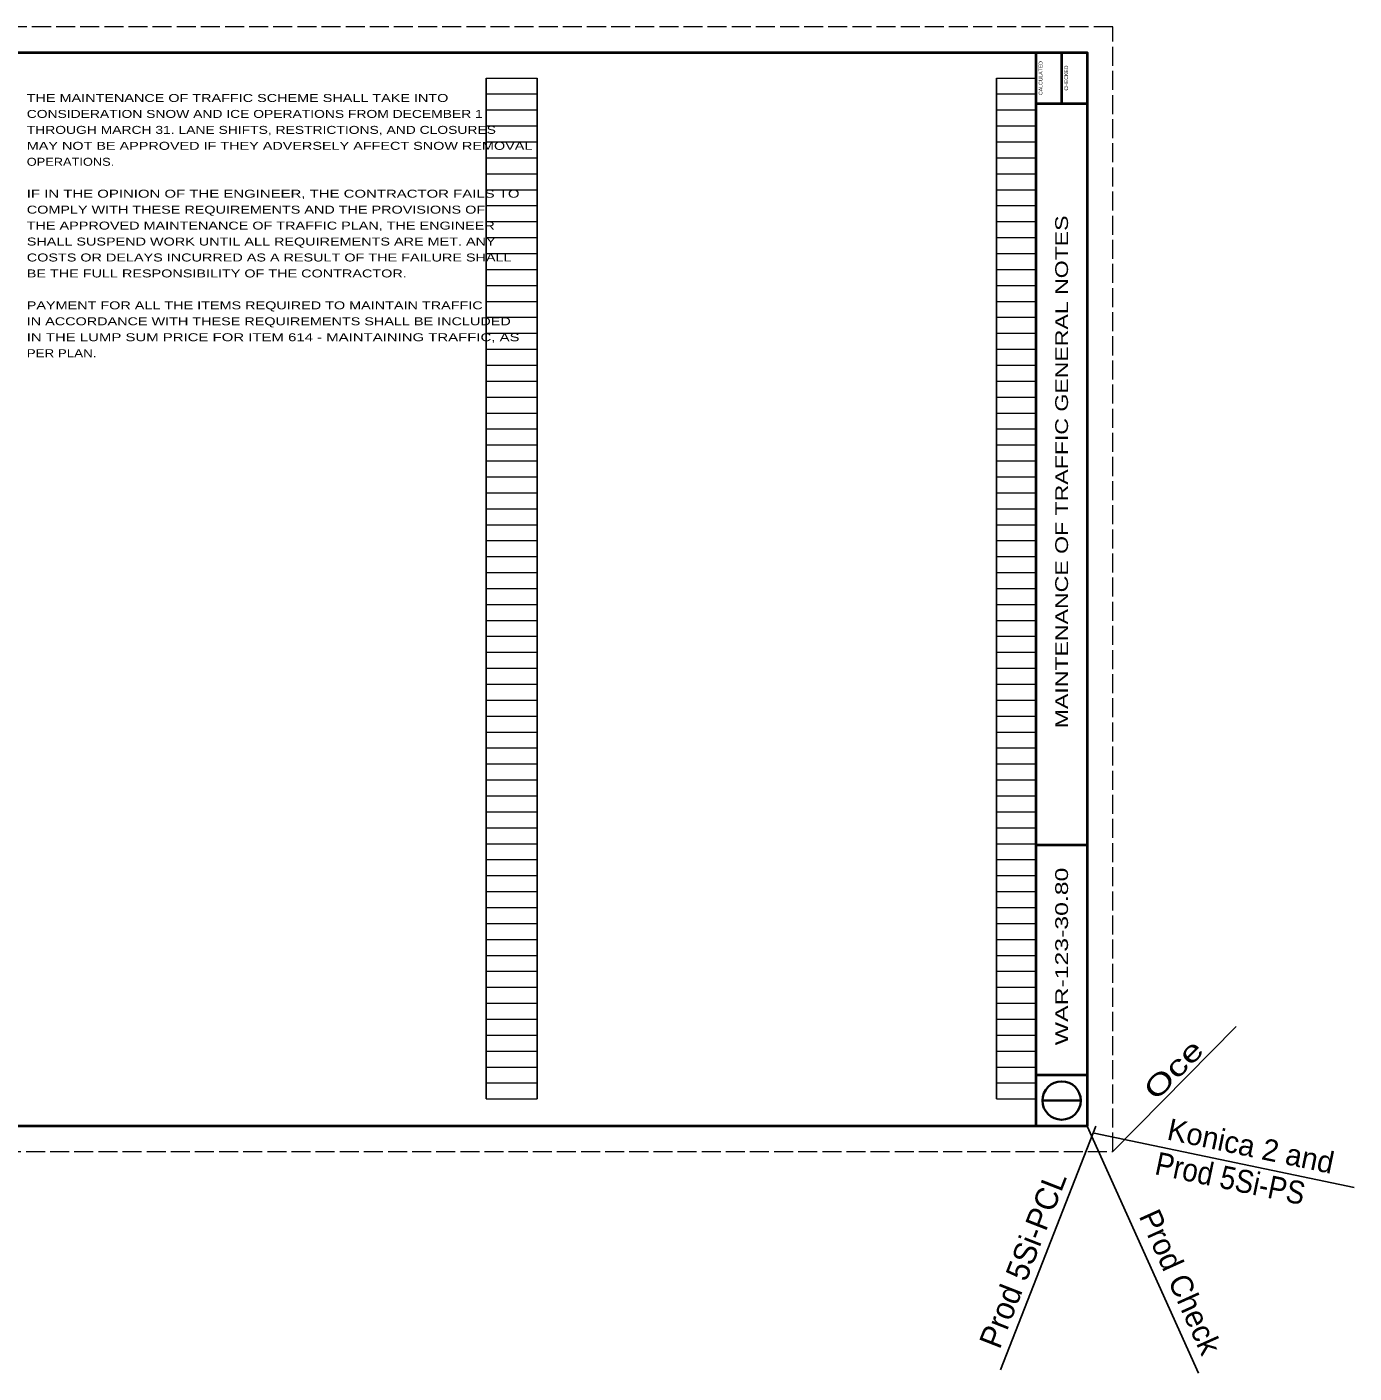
# Model space of a CAD drawing. Extents: x 28.3 to 71.4, y 8.1 to 38.
# Drawn here: x 45.44 to 71.39, y 8.14 to 34.47 of the extents above; entities that cross this region are included whole.
import ezdxf
from ezdxf.enums import TextEntityAlignment as Align

# ---------------------------------------------------------------- set-up
doc = ezdxf.new("R2010")
doc.units = 0
doc.header["$LTSCALE"] = 0.062
doc.linetypes.add('LONG_DASHED', pattern=[7.5, 6, -1.5])
doc.layers.add('1', color=7, linetype='Continuous', lineweight=13)
doc.layers.add('43', color=7, linetype='Continuous', lineweight=25)
doc.layers.add('44', color=7, linetype='Continuous')

msp = doc.modelspace()

# ---------------------------------------------------------------- linework, layer by layer
at = {"layer": '1', "lineweight": 40}
for p, q in [((65.17442, 12.96608), (65.17442, 33.96608)), ((65.67442, 33.96608), (65.67442, 32.96608)), ((65.17442, 32.96608), (66.17442, 32.96608)), ((65.17442, 18.46608), (66.17442, 18.46608)), ((65.17442, 13.96608), (66.17442, 13.96608))]:
    msp.add_line(p, q, dxfattribs=at)
at = {"layer": '1'}
for p, q in [((54.41642, 33.46608), (55.41642, 33.46608)), ((64.40042, 33.46608), (65.17442, 33.46608)), ((54.41642, 33.15408), (55.41642, 33.15408)), ((64.40042, 33.15408), (65.17442, 33.15408)), ((54.41642, 32.84208), (55.41642, 32.84208)), ((64.40042, 32.84208), (65.17442, 32.84208)), ((54.41642, 32.53008), (55.41642, 32.53008)), ((64.40042, 32.53008), (65.17442, 32.53008)), ((54.41642, 32.21808), (55.41642, 32.21808)), ((64.40042, 32.21808), (65.17442, 32.21808)), ((54.41642, 31.90608), (55.41642, 31.90608)), ((64.40042, 31.90608), (65.17442, 31.90608)), ((54.41642, 31.59408), (55.41642, 31.59408)), ((64.40042, 31.59408), (65.17442, 31.59408)), ((54.41642, 31.28208), (55.41642, 31.28208)), ((64.40042, 31.28208), (65.17442, 31.28208)), ((54.41642, 30.97008), (55.41642, 30.97008)), ((64.40042, 30.97008), (65.17442, 30.97008)), ((54.41642, 30.65808), (55.41642, 30.65808)), ((64.40042, 30.65808), (65.17442, 30.65808)), ((54.41642, 30.34608), (55.41642, 30.34608)), ((64.40042, 30.34608), (65.17442, 30.34608)), ((54.41642, 30.03408), (55.41642, 30.03408)), ((64.40042, 30.03408), (65.17442, 30.03408)), ((54.41642, 29.72208), (55.41642, 29.72208)), ((64.40042, 29.72208), (65.17442, 29.72208)), ((54.41642, 29.41008), (55.41642, 29.41008)), ((64.40042, 29.41008), (65.17442, 29.41008)), ((54.41642, 29.09808), (55.41642, 29.09808)), ((64.40042, 29.09808), (65.17442, 29.09808)), ((54.41642, 28.78608), (55.41642, 28.78608)), ((64.40042, 28.78608), (65.17442, 28.78608)), ((54.41642, 28.47408), (55.41642, 28.47408)), ((64.40042, 28.47408), (65.17442, 28.47408)), ((54.41642, 28.16208), (55.41642, 28.16208)), ((64.40042, 28.16208), (65.17442, 28.16208)), ((54.41642, 27.85008), (55.41642, 27.85008)), ((64.40042, 27.85008), (65.17442, 27.85008)), ((54.41642, 27.53808), (55.41642, 27.53808)), ((64.40042, 27.53808), (65.17442, 27.53808)), ((54.41642, 27.22608), (55.41642, 27.22608)), ((64.40042, 27.22608), (65.17442, 27.22608)), ((54.41642, 26.91408), (55.41642, 26.91408)), ((64.40042, 26.91408), (65.17442, 26.91408)), ((54.41642, 26.60208), (55.41642, 26.60208)), ((64.40042, 26.60208), (65.17442, 26.60208)), ((54.41642, 26.29008), (55.41642, 26.29008)), ((64.40042, 26.29008), (65.17442, 26.29008)), ((54.41642, 25.97808), (55.41642, 25.97808)), ((64.40042, 25.97808), (65.17442, 25.97808)), ((54.41642, 25.66608), (55.41642, 25.66608)), ((64.40042, 25.66608), (65.17442, 25.66608)), ((54.41642, 25.35408), (55.41642, 25.35408)), ((64.40042, 25.35408), (65.17442, 25.35408)), ((54.41642, 25.04208), (55.41642, 25.04208)), ((64.40042, 25.04208), (65.17442, 25.04208)), ((54.41642, 24.73008), (55.41642, 24.73008)), ((64.40042, 24.73008), (65.17442, 24.73008)), ((54.41642, 24.41808), (55.41642, 24.41808)), ((64.40042, 24.41808), (65.17442, 24.41808)), ((54.41642, 24.10608), (55.41642, 24.10608)), ((64.40042, 24.10608), (65.17442, 24.10608)), ((54.41642, 23.79408), (55.41642, 23.79408)), ((64.40042, 23.79408), (65.17442, 23.79408)), ((54.41642, 23.48208), (55.41642, 23.48208)), ((64.40042, 23.48208), (65.17442, 23.48208)), ((54.41642, 23.17008), (55.41642, 23.17008)), ((64.40042, 23.17008), (65.17442, 23.17008)), ((54.41642, 22.85808), (55.41642, 22.85808)), ((64.40042, 22.85808), (65.17442, 22.85808)), ((54.41642, 22.54608), (55.41642, 22.54608)), ((64.40042, 22.54608), (65.17442, 22.54608)), ((54.41642, 22.23408), (55.41642, 22.23408)), ((64.40042, 22.23408), (65.17442, 22.23408)), ((54.41642, 21.92208), (55.41642, 21.92208)), ((64.40042, 21.92208), (65.17442, 21.92208)), ((54.41642, 21.61008), (55.41642, 21.61008)), ((64.40042, 21.61008), (65.17442, 21.61008)), ((54.41642, 21.29808), (55.41642, 21.29808)), ((64.40042, 21.29808), (65.17442, 21.29808)), ((54.41642, 20.98608), (55.41642, 20.98608)), ((64.40042, 20.98608), (65.17442, 20.98608)), ((54.41642, 20.67408), (55.41642, 20.67408)), ((64.40042, 20.67408), (65.17442, 20.67408)), ((54.41642, 20.36208), (55.41642, 20.36208)), ((64.40042, 20.36208), (65.17442, 20.36208)), ((54.41642, 20.05008), (55.41642, 20.05008)), ((64.40042, 20.05008), (65.17442, 20.05008)), ((54.41642, 19.73808), (55.41642, 19.73808)), ((64.40042, 19.73808), (65.17442, 19.73808)), ((54.41642, 19.42608), (55.41642, 19.42608)), ((64.40042, 19.42608), (65.17442, 19.42608)), ((54.41642, 19.11408), (55.41642, 19.11408)), ((64.40042, 19.11408), (65.17442, 19.11408)), ((54.41642, 18.80208), (55.41642, 18.80208)), ((64.40042, 18.80208), (65.17442, 18.80208)), ((54.41642, 18.49008), (55.41642, 18.49008)), ((64.40042, 18.49008), (65.17442, 18.49008)), ((54.41642, 18.17808), (55.41642, 18.17808)), ((64.40042, 18.17808), (65.17442, 18.17808)), ((54.41642, 17.86608), (55.41642, 17.86608)), ((64.40042, 17.86608), (65.17442, 17.86608)), ((54.41642, 17.55408), (55.41642, 17.55408)), ((64.40042, 17.55408), (65.17442, 17.55408)), ((54.41642, 17.24208), (55.41642, 17.24208)), ((64.40042, 17.24208), (65.17442, 17.24208)), ((54.41642, 16.93008), (55.41642, 16.93008)), ((64.40042, 16.93008), (65.17442, 16.93008)), ((54.41642, 16.61808), (55.41642, 16.61808)), ((64.40042, 16.61808), (65.17442, 16.61808)), ((54.41642, 16.30608), (55.41642, 16.30608)), ((64.40042, 16.30608), (65.17442, 16.30608)), ((54.41642, 15.99408), (55.41642, 15.99408)), ((64.40042, 15.99408), (65.17442, 15.99408)), ((54.41642, 15.68208), (55.41642, 15.68208)), ((64.40042, 15.68208), (65.17442, 15.68208)), ((54.41642, 15.37008), (55.41642, 15.37008)), ((64.40042, 15.37008), (65.17442, 15.37008)), ((54.41642, 15.05808), (55.41642, 15.05808)), ((64.40042, 15.05808), (65.17442, 15.05808)), ((54.41642, 14.74608), (55.41642, 14.74608)), ((64.40042, 14.74608), (65.17442, 14.74608)), ((54.41642, 14.43408), (55.41642, 14.43408)), ((64.40042, 14.43408), (65.17442, 14.43408)), ((54.41642, 14.12208), (55.41642, 14.12208)), ((64.40042, 14.12208), (65.17442, 14.12208)), ((54.41642, 13.81008), (55.41642, 13.81008)), ((64.40042, 13.81008), (65.17442, 13.81008)), ((54.41642, 13.49808), (55.41642, 13.49808)), ((64.40042, 13.49808), (65.17442, 13.49808))]:
    msp.add_line(p, q, dxfattribs=at)
at = {"layer": '1', "lineweight": 25}
for p, q in [((54.41642, 13.49808), (54.41642, 33.46608)), ((55.41642, 13.49808), (55.41642, 33.46608)), ((64.40042, 13.49808), (64.40042, 33.46608)), ((65.17442, 13.49808), (65.17442, 33.46608))]:
    msp.add_line(p, q, dxfattribs=at)
at = {"layer": '1', "lineweight": 35}
msp.add_line((65.29942, 13.46608), (66.04942, 13.46608), dxfattribs=at)
at = {"layer": '1', "linetype": 'LONG_DASHED'}
msp.add_lwpolyline([(32.67442, 12.46608), (66.67442, 12.46608), (66.67442, 34.46608), (32.67442, 34.46608)], close=True, dxfattribs=at)
at = {"layer": '1', "lineweight": 40}
msp.add_lwpolyline([(34.67442, 33.96608), (66.17442, 33.96608), (66.17442, 12.96608), (34.67442, 12.96608)], close=True, dxfattribs=at)
at = {"layer": '1', "lineweight": 35}
msp.add_circle((65.67441, 13.46604), 0.375, dxfattribs=at)
at = {"layer": '43'}
for p, q in [((66.67442, 12.46608), (69.08942, 14.91683)), ((66.34108, 12.96608), (64.47908, 8.20025)), ((66.17442, 12.96608), (68.35, 8.13525)), ((66.31275, 12.82775), (71.39475, 11.76483))]:
    msp.add_line(p, q, dxfattribs=at)

# ---------------------------------------------------------------- texts
at = {"layer": '1'}
msp.add_text('CALCULATED', height=0.0725, rotation=90, dxfattribs=at).set_placement((65.29942, 33.466), align=Align.CENTER)
for s, height, width, p in [('CHECKED', 0.0725, 0.95, (65.79942, 33.46608)), ('MAINTENANCE OF TRAFFIC GENERAL NOTES', 0.25, 1.35, (65.79942, 25.76329)), ('  WAR-123-30.80 ', 0.25, 1.45, (65.79942, 16.21608))]:
    msp.add_text(s, height=height, rotation=90, dxfattribs=dict(at, width=width)).set_placement(p, align=Align.CENTER)
at = {"layer": '43'}
for s, height, rotation, width, p in [('Oce', 0.4, 45.421, 1.4, (67.52275, 13.44583)), ('Prod 5Si-PS', 0.4484, 348.187, 0.9, (67.47608, 12.0285))]:
    msp.add_text(s, height=height, rotation=rotation, dxfattribs=dict(at, width=width)).set_placement(p)
for s, height, rotation, p in [('Konica 2 and', 0.4232, 348.187, (67.71592, 12.707)), ('Prod 5Si-PCL', 0.4442, 68.66, (64.46242, 8.58308)), ('Prod Check', 0.4329, 294.245, (67.17733, 11.20775))]:
    msp.add_text(s, height=height, rotation=rotation, dxfattribs=at).set_placement(p)
at = {"layer": '44'}
for s, width, p in [('THE MAINTENANCE OF TRAFFIC SCHEME SHALL TAKE INTO ', 1.35, (45.43242, 32.99808)), ('CONSIDERATION SNOW AND ICE OPERATIONS FROM DECEMBER 1 ', 1.3, (45.43242, 32.68608)), ('THROUGH MARCH 31. LANE SHIFTS, RESTRICTIONS, AND CLOSURES ', 1.3, (45.43242, 32.37408)), ('MAY NOT BE APPROVED IF THEY ADVERSELY AFFECT SNOW REMOVAL ', 1.35, (45.43242, 32.06208)), ('OPERATIONS.', 1.2, (45.43242, 31.75008)), ('IF IN THE OPINION OF THE ENGINEER, THE CONTRACTOR FAILS TO ', 1.4, (45.43242, 31.12608)), ('COMPLY WITH THESE REQUIREMENTS AND THE PROVISIONS OF ', 1.35, (45.43242, 30.81408)), ('THE APPROVED MAINTENANCE OF TRAFFIC PLAN, THE ENGINEER ', 1.35, (45.43242, 30.50208)), ('SHALL SUSPEND WORK UNTIL ALL REQUIREMENTS ARE MET. ANY ', 1.35, (45.43242, 30.19008)), ('COSTS OR DELAYS INCURRED AS A RESULT OF THE FAILURE SHALL ', 1.35, (45.43242, 29.87808)), ('BE THE FULL RESPONSIBILITY OF THE CONTRACTOR.', 1.35, (45.43242, 29.56608)), ('PAYMENT FOR ALL THE ITEMS REQUIRED TO MAINTAIN TRAFFIC ', 1.35, (45.43242, 28.94208)), ('IN ACCORDANCE WITH THESE REQUIREMENTS SHALL BE INCLUDED ', 1.35, (45.43242, 28.63008)), ('IN THE LUMP SUM PRICE FOR ITEM 614 - MAINTAINING TRAFFIC, AS ', 1.4, (45.43242, 28.31808)), ('PER PLAN.', 1.25, (45.43242, 28.00608))]:
    msp.add_text(s, height=0.156, dxfattribs=dict(at, width=width)).set_placement(p)

doc.saveas('drawing.dxf')
